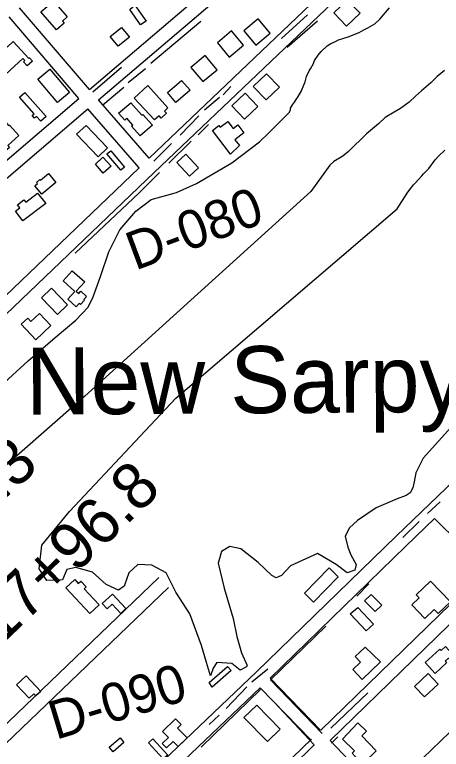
# Model space of a CAD drawing. Extents: x 3568792 to 3606828, y 529143 to 554785.
# Drawn here: x 3579728 to 3580651, y 538456 to 540044 of the extents above; entities that cross this region are included whole.
import ezdxf

# ---------------------------------------------------------------- set-up
doc = ezdxf.new("R2010")
doc.units = 0
for name, color, linetype in [('V-BLDG-OTLN', 7, 'Continuous'), ('V-RIVR-RANG-IDEN', 7, 'Continuous'), ('V-ROAD-CNTR', 7, 'Continuous'), ('V-SITE-VEGE', 7, 'Continuous'), ('V-SURV-IDEN', 7, 'Continuous'), ('V-TOPO-GNAM-IDEN', 7, 'Continuous'), ('V-TOPO-SHOR', 7, 'Continuous')]:
    doc.layers.add(name, color=color, linetype=linetype)

msp = doc.modelspace()

# ---------------------------------------------------------------- linework, layer by layer
at = {"layer": 'V-BLDG-OTLN'}
for points in [[(3579812.4, 540072.7), (3579842.2, 540038.8), (3579831.7, 540029.5), (3579835.3, 540025.4), (3579819.1, 540011.2), (3579784.8, 540050.2)], [(3580447.4, 540075.6), (3580418.5, 540047.9), (3580446.1, 540019), (3580475, 540046.7)], [(3579988.1, 540064.2), (3580012.4, 540029.8), (3580000.6, 540021.5), (3579977, 540054.8)], [(3580249.8, 539978.2), (3580280.4, 540003.9), (3580254.7, 540034.6), (3580224.1, 540008.8)], [(3579934.9, 539996.3), (3579959.3, 540016.2), (3579976.3, 539995.3), (3579952, 539975.5)], [(3580192.4, 539952.3), (3580223, 539978), (3580197.3, 540008.6), (3580166.7, 539982.9)], [(3579662.3, 539929.4), (3579705.3, 539968.7), (3579701.4, 539972.9), (3579707.5, 539978.4), (3579711.9, 539973.6), (3579725.2, 539985.9), (3579758.7, 539949.3), (3579760.3, 539950.8), (3579766.9, 539943.5), (3579755.3, 539933), (3579747.2, 539941.9), (3579750.4, 539944.8), (3579746.3, 539949.3), (3579690, 539898.1)], [(3580135.3, 539899.1), (3580165.9, 539924.9), (3580140.1, 539955.5), (3580109.5, 539929.7)], [(3579804.6, 539926.1), (3579847.1, 539875.4), (3579821.3, 539853.8), (3579778.7, 539904.7)], [(3580273.1, 539916.1), (3580244.2, 539888.5), (3580271.8, 539859.6), (3580300.8, 539887.2)], [(3580108, 539880.4), (3580076.9, 539854.3), (3580058.8, 539875.9), (3580089.1, 539901.3)], [(3580016.2, 539890.4), (3580059.5, 539842.5), (3580052.2, 539835.6), (3580056.8, 539830.7), (3580045.4, 539820), (3580040.5, 539825.2), (3580030.9, 539816.2), (3579986.6, 539863.5)], [(3579750.6, 539875.8), (3579796.4, 539824), (3579784.7, 539813.7), (3579775.7, 539823.9), (3579771.5, 539820.1), (3579766.2, 539826.1), (3579770.4, 539829.8), (3579738.7, 539865.7)], [(3580226.4, 539874.5), (3580197.5, 539846.9), (3580225.2, 539818), (3580254.1, 539845.6)], [(3579979.6, 539853.4), (3580003.4, 539826.5), (3580005.5, 539828.4), (3580026, 539805.2), (3579999.5, 539781.8), (3579981.1, 539802.6), (3579984, 539805.1), (3579971.1, 539819.8), (3579966.3, 539815.5), (3579952.8, 539830.9)], [(3579699.5, 539741.1), (3579662.1, 539783.6), (3579683, 539802.1), (3579691.7, 539792.2), (3579710.9, 539809.1), (3579715.8, 539803.5), (3579717.5, 539805), (3579737.4, 539782.4), (3579713.4, 539761.2), (3579717.1, 539756.9)], [(3579882.7, 539804.1), (3579928.9, 539755.7), (3579908.6, 539736.3), (3579861.8, 539785.4)], [(3580194.9, 539742.6), (3580155.9, 539793.7), (3580170, 539804.5), (3580172.9, 539800.8), (3580189.1, 539813.2), (3580200.8, 539798), (3580210.7, 539805.6), (3580224.1, 539788.2), (3580204.7, 539773.3), (3580214.2, 539761)], [(3579919.3, 539736), (3579936.7, 539716.7), (3579919.9, 539701.6), (3579903, 539720.4)], [(3579936.2, 539749.3), (3579966, 539714.4), (3579958.1, 539707.7), (3579927.7, 539743.3)], [(3580098.4, 539742.4), (3580125.8, 539712.7), (3580106.3, 539694.7), (3580078.9, 539724.4)], [(3579817.4, 539680.8), (3579786.8, 539655.7), (3579771.9, 539673.8), (3579777.8, 539678.6), (3579775.6, 539681.4), (3579782.9, 539687.4), (3579783.9, 539686.2), (3579801.8, 539700.9)], [(3579795.5, 539636), (3579746.1, 539598.1), (3579729.9, 539619.2), (3579739.5, 539626.6), (3579734.7, 539632.8), (3579748.5, 539643.3), (3579752.3, 539638.3), (3579777.8, 539657.7)], [(3579853, 539490.5), (3579879.7, 539466.6), (3579861.2, 539446.1), (3579866.8, 539441.2), (3579871.1, 539446), (3579883.8, 539434.6), (3579878.2, 539428.3), (3579879.6, 539427), (3579870.8, 539417.1), (3579867.9, 539419.7), (3579861.5, 539412.7), (3579843.3, 539429.2), (3579858.3, 539445.7), (3579833.1, 539468.6)], [(3579820.9, 539395.6), (3579786.1, 539431.8), (3579808.1, 539453), (3579842.9, 539416.8)], [(3579806.9, 539371.7), (3579773.9, 539341), (3579742.5, 539374.7), (3579756.5, 539387.8), (3579763.1, 539380.7), (3579782, 539398.3)], [(3580354.6, 538793.8), (3580408.5, 538848.2), (3580428, 538828.8), (3580374.1, 538774.4)], [(3579890.9, 538749.6), (3579838.9, 538804.8), (3579858.2, 538823), (3579865.9, 538814.8), (3579871.1, 538819.7), (3579883, 538807.1), (3579878.6, 538802.9), (3579910.8, 538768.5)], [(3580627.7, 538819.6), (3580670.3, 538775.2), (3580643.6, 538749.6), (3580635.4, 538758.2), (3580615.4, 538739), (3580587.3, 538768.2), (3580603.1, 538783.3), (3580596.6, 538790.2)], [(3579939.6, 538791.5), (3579969, 538760.2), (3579957.7, 538749.6), (3579938.9, 538769.6), (3579928.3, 538759.5), (3579917.4, 538771.1)], [(3580499.1, 538790.9), (3580522, 538768), (3580507.8, 538753.8), (3580484.5, 538777.2)], [(3580470.3, 538762.5), (3580504.2, 538726.8), (3580488.5, 538712), (3580453.6, 538748.9)], [(3580519.2, 538644.9), (3580479.4, 538607.4), (3580459.4, 538628.7), (3580475.8, 538644.3), (3580464.3, 538656.5), (3580486.3, 538677.2)], [(3580637.8, 538619.7), (3580615.8, 538643.5), (3580647.3, 538672.6), (3580650.2, 538669.4), (3580659.6, 538678), (3580690.6, 538644.4), (3580681.8, 538636.4), (3580666.1, 538653.4), (3580658.9, 538646.7), (3580661.9, 538643.4)], [(3580148.7, 538600.2), (3580188.6, 538635), (3580196.2, 538626.3), (3580155.5, 538590.8)], [(3579753.4, 538615), (3579784.6, 538581.4), (3579774.2, 538571.6), (3579770.1, 538576), (3579759.8, 538566.4), (3579732.6, 538595.6)], [(3580622.2, 538620.2), (3580643.7, 538597.3), (3580614.1, 538569.5), (3580592.8, 538592.1)], [(3580251.7, 538551.9), (3580302.4, 538499.8), (3580274.7, 538472.9), (3580223.8, 538525.2)], [(3580047.8, 538494.4), (3580075.9, 538522.1), (3580088.3, 538509.5), (3580080.7, 538502), (3580101.2, 538481.1), (3580081.9, 538462.2), (3580070.8, 538473.4), (3580056.3, 538459.2), (3580047.2, 538468.5), (3580060.6, 538481.7)], [(3580436.8, 538477.9), (3580470.3, 538513.2), (3580488.9, 538495.5), (3580479.1, 538485.1), (3580510.1, 538452.7), (3580484.7, 538428.5), (3580475.7, 538438), (3580471.1, 538433.6), (3580457.7, 538447.6), (3580462.9, 538452.6)], [(3579964.6, 538470.9), (3579941.3, 538450.8), (3579932.6, 538461), (3579956.1, 538481.3)], [(3580049.5, 538435.3), (3580017.5, 538470), (3580026.9, 538478.6), (3580059.3, 538443.5)]]:
    msp.add_lwpolyline(points, close=True, dxfattribs=at)
at = {"layer": 'V-ROAD-CNTR'}
for p, q in [((3579890, 539882.3), (3580538.9, 540435.5)), ((3579909.6, 539859.5), (3580558.4, 540412.6)), ((3580617.4, 540303.9), (3580018.9, 539733.5)), ((3579890, 539882.3), (3579739, 540058.8)), ((3579867.2, 539862.8), (3579716.3, 540039.3)), ((3580018.9, 539733.5), (3579909.6, 539859.6)), ((3579997.2, 539712.8), (3579886.8, 539840.1)), ((3579997.2, 539712.8), (3579063.7, 538820.1)), ((3580524.5, 538354.8), (3580881.8, 538697)), ((3580389.9, 538497.2), (3580280.5, 538610.1)), ((3579896.5, 538244.1), (3580258.9, 538589.3)), ((3580368.3, 538476.4), (3580258.9, 538589.3)), ((3580370.4, 538477.9), (3580003.9, 538128.7)), ((3580524.5, 538354.8), (3580410.6, 538475.5))]:
    msp.add_line(p, q, dxfattribs=at)
for points in [[(3580638.1, 540282.2), (3580029.9, 539702.5), (3579084.5, 538798.4)], [(3578936.1, 539066.7), (3579867.1, 539862.7)], [(3578955.6, 539043.9), (3579886.8, 539840.1)], [(3579865.1, 538255.7), (3580251.2, 538623.4), (3580553, 538916.7), (3580823.8, 539177)], [(3580280.5, 538610.1), (3580573.9, 538895.1), (3580636.1, 538954.9)], [(3580636.1, 538954.9), (3580748, 538844.8)], [(3580748, 538844.8), (3580390, 538497.3)], [(3579263.7, 538083.7), (3580040.2, 538827.7)], [(3580769.4, 538823.7), (3580410.6, 538475.5)], [(3579284.5, 538062.1), (3580061, 538806)]]:
    msp.add_lwpolyline(points, dxfattribs=at)
at = {"layer": 'V-SITE-VEGE'}
for points in [[(3579706.2, 539248.6), (3579757.7, 539295.9), (3579816.2, 539346), (3579860.8, 539383.6), (3579887.3, 539411.5), (3579898.4, 539433.7), (3579913.7, 539478.3), (3579931.8, 539531.2), (3579955.5, 539578.6), (3579990.3, 539618.9), (3580023.8, 539644), (3580078.1, 539659.3), (3580121.2, 539678.8), (3580197.8, 539723.3), (3580257.7, 539769.3), (3580276.9, 539787.7), (3580322.2, 539832.9), (3580324.5, 539838.6), (3580324.5, 539842), (3580329, 539848.8), (3580333.6, 539854.4), (3580338.1, 539862.3), (3580340.4, 539865.7), (3580348.3, 539879.3), (3580349.4, 539881.6), (3580356.2, 539898.6), (3580359.6, 539909.9), (3580365.3, 539922.3), (3580367.6, 539926.9), (3580374.3, 539938.2), (3580376.6, 539945), (3580384.5, 539956.3), (3580391.3, 539964.2), (3580403.8, 539976.7), (3580411.7, 539981.2), (3580421.9, 539985.7), (3580428.7, 539989.1), (3580437.8, 539992.5), (3580449.1, 539995.9), (3580472.9, 540005), (3580483, 540010.7), (3580492.1, 540015.2), (3580506.8, 540024.2), (3580518.1, 540034.4), (3580526.1, 540043.5), (3580538.5, 540058.2)], [(3580657.4, 539923.4), (3580641.5, 539909.9), (3580628, 539896.3), (3580607.6, 539879.3), (3580595.1, 539868), (3580581.5, 539854.4), (3580562.3, 539840.8), (3580548.7, 539832.9), (3580529.4, 539821.6), (3580514.7, 539808), (3580488.7, 539786.5), (3580450.2, 539748), (3580437.7, 539737.8), (3580418.5, 539726.5), (3580409.4, 539718.5), (3580368.6, 539661.5)], [(3580678.1, 539158.6), (3580611.3, 539085.5), (3580596, 539053.5), (3580591.8, 539034), (3580589, 539021.4), (3580583.5, 539010.3), (3580575.1, 539004.7), (3580555.6, 538997.8), (3580509.6, 538978.3), (3580469.3, 538950.4), (3580452.5, 538935.1), (3580442.8, 538917), (3580448.4, 538893.3), (3580455.3, 538876.6), (3580466.5, 538855.7), (3580463.7, 538843.2), (3580447, 538837.6), (3580423.3, 538855.7), (3580382.9, 538879.4), (3580324.4, 538853), (3580304.9, 538832.1), (3580293.8, 538826.5), (3580284, 538832.1), (3580254.8, 538860), (3580217.2, 538889.2), (3580193.5, 538894.8), (3580175.4, 538883.6), (3580168.5, 538858.6), (3580181, 538804.3), (3580200.5, 538738.8), (3580208.8, 538699.8), (3580218.6, 538665), (3580231.1, 538637.2), (3580229.7, 538634.4), (3580215.8, 538627.4), (3580197.7, 538641.3), (3580165.6, 538644.1), (3580157.3, 538631.6), (3580151.7, 538614.9), (3580143.3, 538644.1), (3580132.2, 538680.3), (3580107.2, 538748.6), (3580076.5, 538795.9), (3580055.7, 538837.7), (3580025, 538854.4), (3579994.4, 538855.8), (3579974.9, 538837.7), (3579965.1, 538808.5), (3579952.6, 538800.1), (3579926.1, 538812.7), (3579896.9, 538839.1), (3579860.7, 538848.9), (3579841.2, 538844.7), (3579831.5, 538822.4), (3579798, 538821), (3579781.3, 538846.1), (3579786.9, 538897.6), (3579846.8, 538970), (3580076.6, 539215.1), (3580555.3, 539624.3), (3580577, 539657.9), (3580582.7, 539665.9), (3580590.6, 539676), (3580594, 539679.4), (3580608.8, 539695.3), (3580612.2, 539699.8), (3580623.5, 539711.1), (3580637.1, 539730.4), (3580645, 539738.3), (3580658.6, 539750.8)], [(3580368.6, 539661.5), (3579880.3, 539219.3), (3579461, 538851.7)]]:
    msp.add_lwpolyline(points, dxfattribs=at)
at = {"layer": 'V-TOPO-SHOR'}
for p, q in [((3580305.4, 539992.5), (3580361.5, 540043.5)), ((3580023, 539939.2), (3580130.5, 540029.4)), ((3580317.6, 539973.4), (3580382.8, 540030.8)), ((3579897.2, 539877.2), (3579959.1, 539930.5)), ((3579973.8, 539897.3), (3580011.2, 539927.8)), ((3579918.7, 539848.6), (3579964.2, 539887.3)), ((3580178.8, 539870.9), (3580195.6, 539888.6)), ((3580139.1, 539838.1), (3580171.5, 539865.4)), ((3580086.3, 539783.4), (3580126.8, 539824.9)), ((3580125.4, 539783.9), (3580147.7, 539806.7)), ((3580062, 539722.9), (3580109.9, 539770.7)), ((3580029.3, 539726.9), (3580067.2, 539765.2)), ((3580621, 538966.1), (3580648.3, 538990.7)), ((3580567.2, 538914.1), (3580602.7, 538948.8)), ((3580467.9, 538787.1), (3580494.3, 538813.5)), ((3580281.5, 538606.3), (3580400.9, 538722.4)), ((3580241.4, 538601.7), (3580275.6, 538630.4)), ((3580281.5, 538606.3), (3580393.1, 538490.1)), ((3580131.3, 538460.8), (3580259.8, 538585.1)), ((3580185.8, 538544.3), (3580230, 538591.2)), ((3580412.2, 538501.9), (3580492, 538578.4)), ((3580289.4, 538558.2), (3580375.5, 538465.7)), ((3580148.9, 538509.7), (3580170.3, 538529.7)), ((3580413.2, 538469.1), (3580426.9, 538483.2)), ((3580233.3, 538326.4), (3580375.5, 538465.7))]:
    msp.add_line(p, q, dxfattribs=at)
msp.add_lwpolyline([(3579859.3, 539528.4), (3579997.3, 539659.1), (3580041.5, 539702.9)], dxfattribs=at)

# ---------------------------------------------------------------- texts
at = {"layer": 'V-RIVR-RANG-IDEN'}
for s, rotation, p in [('D-080', 20.4123, (3579989, 539490.3)), ('D-090', 16.8793, (3579817.3, 538476.4))]:
    msp.add_text(s, height=83, rotation=rotation, dxfattribs=at).set_placement(p)
at = {"layer": 'V-SURV-IDEN'}
for s, rotation, p in [('5416+21.3', 41.8035, (3579310.1, 538641.8)), ('5417+96.8', 43.7944, (3579589.7, 538575.4))]:
    msp.add_text(s, height=100, rotation=rotation, dxfattribs=at).set_placement(p)
at = {"layer": 'V-TOPO-GNAM-IDEN'}
msp.add_text('New Sarpy', height=145, rotation=0.3783, dxfattribs=at).set_placement((3579752.9, 539179.2))

doc.saveas('drawing.dxf')
